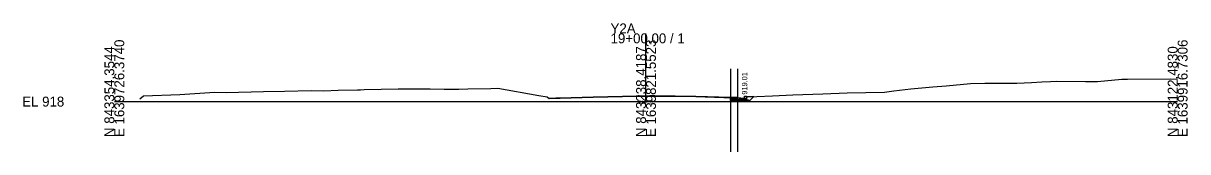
# Model space of a CAD drawing. Extents: x -26 to 303, y -10 to 10517.
# Drawn here: x -25.7 to 302.8, y 8485.9 to 8522.1 of the extents above; entities that cross this region are included whole.
import ezdxf

# ---------------------------------------------------------------- set-up
doc = ezdxf.new("R2010")
doc.units = 0
for name, color, linetype in [('Exist Cross Section Cell', 7, 'Continuous'), ('Exist XS Center Line Elevation Label', 7, 'Continuous'), ('Exist XS Ground Line', 7, 'Continuous'), ('Prop CMT Conc Surface', 7, 'Continuous'), ('Prop CMT Concrete Structures', 7, 'Continuous'), ('Prop CMT Pvmt Course 1', 7, 'Continuous'), ('Prop CMT Pvmt Course 1 CG', 7, 'Continuous'), ('Prop CMT Pvmt Course 2', 7, 'Continuous'), ('Prop CMT Pvmt Surface Overlay', 7, 'Continuous'), ('Prop CMT Slope Grass', 7, 'Continuous'), ('Prop CMT Subgrade Earthwork', 7, 'Continuous'), ('Prop XS Hydro Elevations', 7, 'Continuous'), ('Scratch_Level_0', 7, 'Continuous'), ('Scratch_Level_2', 7, 'Continuous')]:
    doc.layers.add(name, color=color, linetype=linetype)

msp = doc.modelspace()

# ---------------------------------------------------------------- linework, layer by layer
at = {"layer": 'Exist Cross Section Cell'}
for p, q in [((150, 8500), (150, 8519.23)), ((0, 8500), (150, 8500)), ((150, 8500), (300, 8500))]:
    msp.add_line(p, q, dxfattribs=at)
at = {"layer": 'Exist XS Ground Line'}
msp.add_lwpolyline([(7.17, 8500.78), (8.25, 8501.58), (18.48, 8502.04), (28.35, 8502.66), (31.55, 8502.6), (42.07, 8502.88), (48.05, 8502.9), (55.67, 8503.14), (59.14, 8503.07), (63.13, 8503.21), (68.57, 8503.34), (69.48, 8503.35), (70.44, 8503.39), (80.03, 8503.62), (83.22, 8503.61), (89.08, 8503.56), (93.03, 8503.53), (94.83, 8503.49), (97.17, 8503.53), (99.73, 8503.55), (106.24, 8503.65), (108.15, 8503.75), (119.78, 8501.69), (122.16, 8501.34), (122.66, 8500.84), (124.56, 8500.92), (125.74, 8500.96), (135.08, 8501.23), (143.34, 8501.41), (150, 8501.55), (151.04, 8501.57), (152.45, 8501.55), (164.05, 8501.44), (174.63, 8501.04), (176.27, 8500.98), (177.74, 8500.9), (178.16, 8500.88), (178.65, 8501.38), (181.25, 8501.46), (185.67, 8501.65), (191.44, 8501.91), (199.91, 8502.2), (206.78, 8502.48), (217.26, 8502.67), (219.92, 8502.99), (224.76, 8503.57), (230.92, 8504.13), (234.69, 8504.45), (241.59, 8505.12), (245.6, 8505.15), (247.04, 8505.15), (254.65, 8505.21), (258.75, 8505.42), (261.67, 8505.56), (264.08, 8505.68), (265.8, 8505.79), (273.96, 8505.7), (277.39, 8505.68), (284.23, 8506.3), (285.12, 8506.32), (285.87, 8506.32), (297.88, 8506.41), (300, 8506.34)], dxfattribs=at)
at = {"layer": 'Prop CMT Conc Surface'}
msp.add_lwpolyline([(177.81, 8501.01), (177.81, 8501.51), (178.31, 8501.51)], dxfattribs=at)
at = {"layer": 'Prop CMT Concrete Structures'}
for points in [[(175.81, 8501.13), (177.81, 8501.01), (177.81, 8501.51), (178.31, 8501.51)], [(178.31, 8501.51), (178.31, 8500.49), (175.81, 8500.54)]]:
    msp.add_lwpolyline(points, dxfattribs=at)
at = {"layer": 'Prop CMT Pvmt Course 1'}
for p, q in [((173.81, 8501.2), (173.81, 8500.95)), ((175.81, 8501.13), (173.81, 8501.2)), ((175.8, 8500.88), (173.81, 8500.95)), ((175.81, 8501.13), (175.81, 8500.88))]:
    msp.add_line(p, q, dxfattribs=at)
at = {"layer": 'Prop CMT Pvmt Course 1 CG'}
for p, q in [((175.79, 8500.21), (173.79, 8500.29)), ((173.81, 8500.62), (173.81, 8500.29)), ((175.81, 8500.55), (175.81, 8500.21))]:
    msp.add_line(p, q, dxfattribs=at)
for points in [[(175.81, 8500.54), (178.81, 8500.48), (179.15, 8500.15)], [(179.11, 8500.15), (175.81, 8500.21)]]:
    msp.add_lwpolyline(points, dxfattribs=at)
at = {"layer": 'Prop CMT Pvmt Course 2'}
for p, q in [((175.8, 8500.55), (173.8, 8500.62)), ((173.81, 8500.62), (173.81, 8500.95)), ((175.81, 8500.55), (175.81, 8500.88))]:
    msp.add_line(p, q, dxfattribs=at)
at = {"layer": 'Prop CMT Pvmt Surface Overlay'}
msp.add_lwpolyline([(122.54, 8500.96), (124.55, 8501.05), (125.74, 8501.08), (135.07, 8501.36), (143.33, 8501.54), (151.04, 8501.69), (152.45, 8501.68), (164.05, 8501.57), (173.81, 8501.2)], dxfattribs=at)
at = {"layer": 'Prop CMT Slope Grass'}
msp.add_lwpolyline([(178.31, 8501.51), (180.43, 8501.43)], dxfattribs=at)
at = {"layer": 'Prop CMT Subgrade Earthwork'}
msp.add_lwpolyline([(175.81, 8500.21), (179.15, 8500.15), (180.43, 8501.43)], dxfattribs=at)
at = {"layer": 'Scratch_Level_0'}
for p, q in [((173.81, 8509.22), (173.81, 8485.87)), ((175.81, 8509.22), (175.81, 8485.87))]:
    msp.add_line(p, q, dxfattribs=at)
at = {"layer": 'Scratch_Level_2'}
msp.add_line((180.43, 8501.43), (178.65, 8501.38), dxfattribs=at)
for points in [[(173.81, 8501.08), (173.79, 8500.29), (175.79, 8500.21), (179.15, 8500.15), (179.79, 8500.79), (180.43, 8501.43)], [(173.81, 8501.08), (173.79, 8500.29), (175.79, 8500.21), (179.15, 8500.15), (179.79, 8500.79), (180.43, 8501.43)], [(178.65, 8501.38), (178.16, 8500.88), (177.74, 8500.9), (176.27, 8500.98), (174.63, 8501.04), (173.81, 8501.08)]]:
    msp.add_lwpolyline(points, dxfattribs=at)

# ---------------------------------------------------------------- texts
at = {"layer": 'Exist Cross Section Cell'}
for s, p in [('Y2A', (140, 8519.23)), ('19+00.00 / 1', (140, 8516.43)), ('EL 918', (-26, 8498.6))]:
    msp.add_text(s, height=2.8, dxfattribs=at).set_placement(p)
for s, p in [('E 1639726.3740', (2.8, 8490)), ('E 1639821.5523', (152.8, 8490)), ('E 1639916.7306', (302.8, 8490)), ('N 843354.3544', (0, 8490)), ('N 843238.4187', (150, 8490)), ('N 843122.4830', (300, 8490))]:
    msp.add_text(s, height=2.8, rotation=90, dxfattribs=at).set_placement(p)
at = {"layer": 'Exist XS Center Line Elevation Label'}
msp.add_text('919.55', height=1, dxfattribs=at).set_placement((147.84, 8499.34))
at = {"layer": 'Prop XS Hydro Elevations'}
msp.add_text('919.01', height=1.5, rotation=90, dxfattribs=at).set_placement((178.56, 8501.96))

doc.saveas('drawing.dxf')
